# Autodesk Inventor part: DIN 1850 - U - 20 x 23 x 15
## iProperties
Created: 2006-11
Part Number: DIN 1850 - U - 20 x 23 x 15
Material: Stahl, weich, unlegiert
Description: Bundbuchse
Vendor: Autodesk Inc.
Document SubType Name: Modeling
Standard: DIN 1850 - U
Designer: Schmidt
Standards Organization: DIN
Language: de-DE
Size Designation: 20 x 23 x 15
Categories: <MemberInstance Version="R10.0.0"><Categories><Category DisplayName="Wellenteile" InternalName="7f7aeb1f-a693-4053-b835-cee3144e0d98" Mnemonic="SHFT"><Category
Cost Center: 0,011 kg
Authority: 1360 mm^3
Density: 7.86 g/cm^3
SaveDate: 2006-11-05
SaveTime: 23:03
TotalMass: 0,011 kg
TotalVolume: 1360 mm^3
Author: Schmidt
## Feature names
1. Körper [Revolution]
2. Fase1 [Chamfer]
3. Fase2 [Chamfer]
4. Fase3 [Chamfer]
5. Fase4 [Chamfer]
6. Fase5 [Chamfer]
7. Extrusion1
